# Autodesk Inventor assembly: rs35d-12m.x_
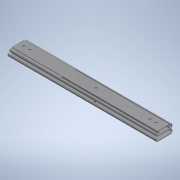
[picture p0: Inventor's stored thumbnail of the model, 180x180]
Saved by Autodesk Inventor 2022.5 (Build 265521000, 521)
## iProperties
Part Number: rs35d-12m.x_
Material: 一般
Document SubType Name: Assembly
Designer: ImaoCorp
Sending System: SOLIDWORKS 2017-2017317
MC: AMD64
MC_MODEL: Intel64 Family 6 Model 60 Stepping 3, GenuineIntel
OS: Windows_NT
FRU: Parasolid Version 29.0, build 201,  4-17-2017
FORMAT: text
GUISE: transmit
KEY: rs35d-12m
FILE: rs35d-12m.x_t
DATE: Tue Feb 05 16:30:04 2019
Author: ImaoCorp
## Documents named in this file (4)
- X:\14_SW2022-Inv2022\00_全2023-1023新製品(TCC)まで\r\rs35d-12m\RS35D-12M.iam
- X:\14_SW2022-Inv2022\00_全2023-1023新製品(TCC)まで\r\rs35d-12m\rs35d-12m_01.ipt
- X:\14_SW2022-Inv2022\00_全2023-1023新製品(TCC)まで\r\rs35d-12m\rs35d-12m_02.ipt
- X:\14_SW2022-Inv2022\00_全2023-1023新製品(TCC)まで\r\rs35d-12m\rs35d-12m_03.ipt
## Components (3 placed, 3 different names)
1. rs35d-12m_01
2. rs35d-12m_02
3. rs35d-12m_03
